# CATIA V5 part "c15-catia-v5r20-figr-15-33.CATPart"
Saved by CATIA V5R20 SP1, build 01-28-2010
Part number: Part1
Bounding box of the stored display mesh (mm): x -40.264 to 42.014, y -25.445 to 25.445, z -51 to 0.75
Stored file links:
  D:\v5_r20\psrt_files_downloaded\c15\c15-catia-v5r20-figr-15-33.CATPart
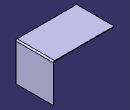
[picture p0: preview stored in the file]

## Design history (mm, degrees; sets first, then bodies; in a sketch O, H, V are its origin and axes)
SheetMetalParameters1: Thickness 0.75, BendRadius 1, KFactor 0.356492 {= log(min(100,max(20*SheetMetalParameters1.BendRadius,SheetMetalParameters1.Thickness)/SheetMetalParameters1.Thickness))/log(100)/2}, ReliefRadialLength 1, ReliefAxialLength 2, MinimumBendRadius 0
Body1 (main body)
  Sketch1 on xy-plane, origin (0, 0, 0), H (1, 0, 0), V (0, 1, 0)
    line L1 (-40.2643, 25.445) -> (40.2643, 25.445)
    line L2 (40.2643, 25.445) -> (40.2643, -25.445)
    line L3 (40.2643, -25.445) -> (-40.2643, -25.445)
    line L4 (-40.2643, -25.445) -> (-40.2643, 25.445)
    horizontal: L1 H, L3 H
    vertical: L2 V, L4 V
    symmetry: L1 L3 H, L4 L2 V
  Wall1: Thickness 0.75, Profile Sketch1
  Flange1: Guide edge [face of Wall1 | face of Wall1], Angle 90, KFacteur 0.356492 {= log(min(100,max(20*Flange1.Radius,SheetMetalParameters1.Thickness)/SheetMetalParameters1.Thickness))/log(100)/2}, Length 50, Radius 1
